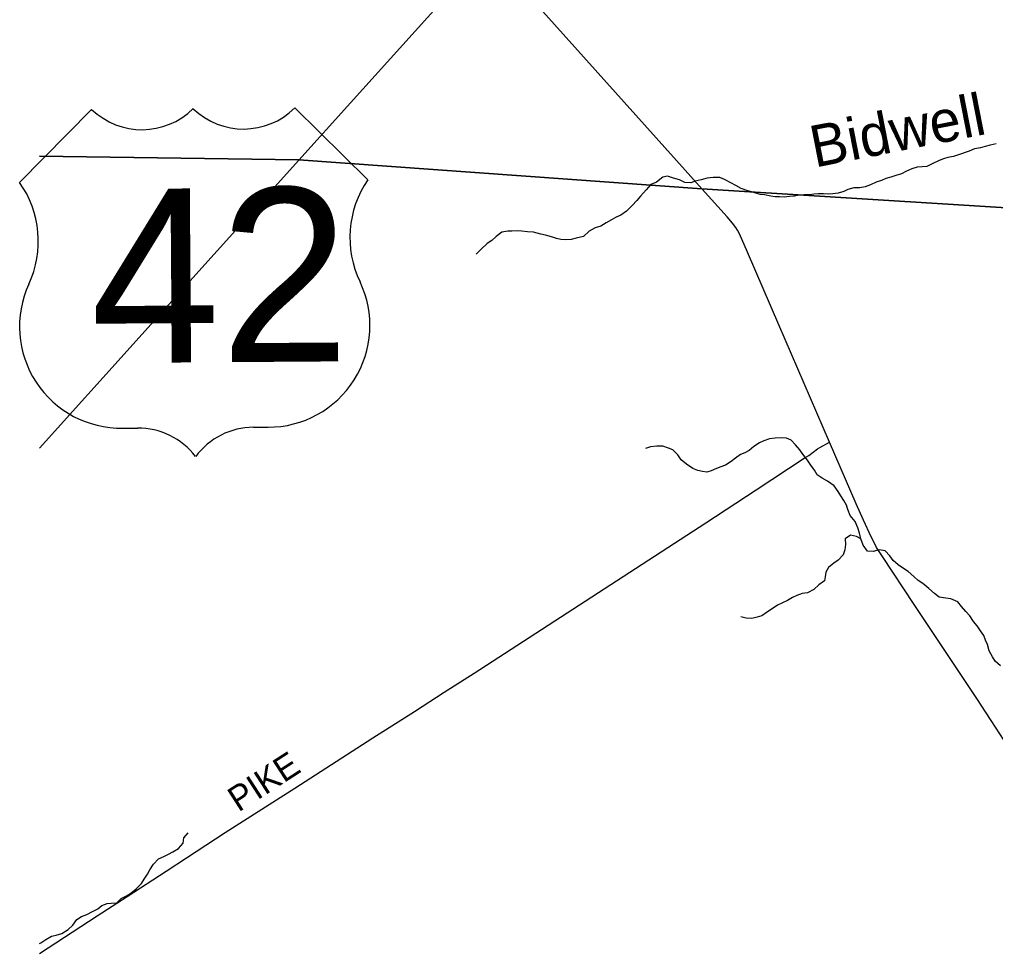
# Model space of a CAD drawing. Extents: x 114604 to 551442, y 316898 to 567001.
# Drawn here: x 114604 to 126312, y 394030 to 405241 of the extents above; entities that cross this region are included whole.
import ezdxf

# ---------------------------------------------------------------- set-up
doc = ezdxf.new("R2010")
doc.units = 0
for name, color, linetype in [('GE_P_Alignment_1000_Stations', 7, 'Continuous'), ('GE_P_Alignment_500_Bearings', 7, 'Continuous'), ('GE_P_Alignment_500_Cardinal_Points', 7, 'Continuous'), ('GE_P_Alignment_500_Distances', 7, 'Continuous'), ('PM_P_Cells', 7, 'Continuous'), ('PM_P_CL_Double_Solid', 7, 'Continuous'), ('PM_P_Stop_Line', 7, 'Continuous'), ('RD_X_RR_1', 7, 'Continuous')]:
    doc.layers.add(name, color=color, linetype=linetype)

msp = doc.modelspace()

# ---------------------------------------------------------------- linework, layer by layer
at = {"layer": 'GE_P_Alignment_1000_Stations'}
for points in [[(117956, 403554), (118576, 404240), (119979, 405801)], [(114843, 400096), (115967, 401345), (116469, 401900), (117956, 403554)]]:
    msp.add_lwpolyline(points, dxfattribs=at)
at = {"layer": 'GE_P_Alignment_500_Bearings'}
for points in [[(122792, 403206), (122590, 403434), (120534, 405730), (120339, 405951), (120260, 406047)], [(124322, 400169), (123713, 401576), (123338, 402450), (123241, 402669), (123217, 402711), (123196, 402745), (123156, 402797), (123092, 402871), (122792, 403206)], [(114843, 394030), (115537, 394481), (115896, 394713), (116363, 395017), (116608, 395180), (117070, 395482), (117905, 396014), (118844, 396617), (119342, 396934), (119699, 397166), (120059, 397395), (120571, 397725), (121846, 398557), (122838, 399201), (123440, 399595), (124015, 399975), (124071, 400009), (124123, 400049), (124177, 400087), (124205, 400104), (124322, 400169)], [(126519, 396426), (126262, 396828), (126090, 397091), (125336, 398220), (124956, 398794), (124886, 398905), (124855, 398962), (124821, 399032), (124730, 399230), (124642, 399428), (124322, 400169)]]:
    msp.add_lwpolyline(points, dxfattribs=at)
at = {"layer": 'GE_P_Alignment_500_Cardinal_Points'}
for p, q in [((115469, 404162), (114605, 403285)), ((118782, 403315), (117906, 404179)), ((115845, 400336), (116019, 400337)), ((117411, 400347), (117585, 400348))]:
    msp.add_line(p, q, dxfattribs=at)
for centre, radius, start, end in [((116074, 404788), 870, 225.984, 314.838), ((117292, 404796), 870, 225.984, 314.838), ((113612, 402580), 1218, 334.9581, 35.4119), ((119785, 402624), 1218, 145.4101, 205.8639), ((115822, 401554), 1218, 155.2429, 271.0493), ((117590, 401566), 1218, 269.7728, 25.5791), ((116025, 399467), 870, 37.2809, 90.411), ((117417, 399477), 870, 90.411, 143.5411)]:
    msp.add_arc(centre, radius, start, end, dxfattribs=at)
at = {"layer": 'GE_P_Alignment_500_Distances'}
for points in [[(114843, 403600), (117955, 403556), (122791, 403209), (132603, 402598)], [(132603, 402598), (122791, 403209), (117955, 403556), (114843, 403600)]]:
    msp.add_lwpolyline(points, dxfattribs=at)
at = {"layer": 'PM_P_Cells'}
for points in [[(126321, 403747), (126247, 403731), (126187, 403715), (126133, 403699), (126059, 403688), (125996, 403660), (125868, 403616), (125810, 403598), (125740, 403583), (125690, 403569), (125635, 403549), (125551, 403509), (125487, 403477), (125431, 403473), (125373, 403470), (125307, 403448), (125244, 403420), (125184, 403390), (125116, 403368), (125056, 403348), (124998, 403333), (124943, 403307), (124881, 403287), (124813, 403257), (124747, 403231), (124685, 403220), (124612, 403220), (124542, 403200), (124492, 403176), (124426, 403158), (124362, 403149), (124312, 403145), (124248, 403147), (124185, 403149), (124133, 403143), (124083, 403137), (124015, 403136), (123951, 403132), (123899, 403122), (123841, 403116), (123775, 403109), (123721, 403111), (123671, 403113), (123618, 403121), (123540, 403137), (123490, 403142), (123414, 403166), (123340, 403184)], [(123340, 403184), (123262, 403213), (123196, 403249), (123136, 403279), (123060, 403320), (123004, 403344), (122926, 403344), (122852, 403336), (122780, 403317), (122710, 403299), (122658, 403279), (122587, 403285), (122520, 403318), (122449, 403338), (122377, 403360), (122321, 403348), (122245, 403289), (122177, 403259), (122120, 403197), (122054, 403121), (122008, 403067), (121953, 403009), (121887, 402941), (121817, 402893), (121760, 402867), (121706, 402836), (121642, 402800), (121578, 402762), (121509, 402742), (121437, 402700), (121371, 402638), (121283, 402617), (121222, 402599), (121148, 402595), (121098, 402599), (121046, 402612), (120986, 402632), (120912, 402654), (120858, 402664), (120770, 402687), (120698, 402693), (120630, 402701), (120574, 402704), (120512, 402702), (120462, 402700), (120391, 402690), (120323, 402638), (120269, 402589), (120215, 402551), (120142, 402485), (120082, 402423)], [(124298, 399698), (124232, 399734), (124174, 399774), (124140, 399830), (124096, 399890), (124056, 399950), (124002, 400023), (123964, 400075), (123914, 400135), (123862, 400191), (123806, 400215), (123746, 400219), (123670, 400215), (123602, 400207), (123534, 400185), (123482, 400161), (123414, 400115), (123356, 400069), (123304, 400039), (123252, 400019), (123194, 399975), (123142, 399935), (123074, 399893), (123016, 399871), (122964, 399851), (122902, 399823), (122848, 399809), (122796, 399815), (122740, 399829), (122683, 399853), (122605, 399905), (122541, 399955), (122501, 400017), (122443, 400075), (122391, 400095), (122321, 400119), (122249, 400119), (122175, 400112), (122115, 400092)], [(126373, 397482), (126307, 397540), (126275, 397590), (126237, 397664), (126215, 397740), (126193, 397792), (126171, 397846), (126131, 397903), (126093, 397961), (126049, 398015), (126004, 398081), (125956, 398135), (125906, 398195), (125862, 398251), (125778, 398289), (125716, 398295), (125638, 398307), (125580, 398353), (125514, 398412), (125442, 398470), (125386, 398506), (125332, 398556), (125264, 398614), (125198, 398660), (125146, 398694), (125086, 398746), (125043, 398802), (124989, 398862), (124915, 398874), (124843, 398856), (124775, 398859), (124725, 398931), (124697, 399009), (124681, 399077), (124659, 399141), (124627, 399217), (124569, 399289), (124541, 399361), (124523, 399413), (124491, 399468), (124455, 399524), (124423, 399574), (124377, 399642), (124298, 399698)], [(124697, 399007), (124645, 399035), (124573, 399051), (124509, 399009), (124511, 398941), (124505, 398877), (124483, 398817), (124425, 398750), (124373, 398714), (124309, 398662), (124275, 398608), (124267, 398552), (124261, 398502), (124193, 398454), (124131, 398398), (124057, 398358), (123991, 398352), (123929, 398328), (123875, 398304), (123815, 398266), (123749, 398236), (123697, 398212), (123647, 398174), (123579, 398130), (123509, 398084), (123455, 398068), (123389, 398052), (123323, 398056), (123259, 398070)], [(114843, 394149), (114859, 394158), (114919, 394200), (114987, 394238), (115045, 394252), (115113, 394272), (115189, 394320), (115245, 394372), (115291, 394438), (115347, 394476), (115413, 394498), (115481, 394534), (115543, 394568), (115593, 394608), (115655, 394632), (115705, 394636), (115773, 394640), (115823, 394690), (115889, 394724), (115941, 394756), (116005, 394806), (116069, 394872), (116101, 394924), (116141, 394984), (116169, 395036), (116213, 395102), (116271, 395166), (116337, 395196), (116391, 395224), (116445, 395250), (116513, 395291), (116569, 395355), (116577, 395419), (116629, 395479)]]:
    msp.add_lwpolyline(points, dxfattribs=at)

# ---------------------------------------------------------------- texts
at = {"layer": 'GE_P_Alignment_500_Cardinal_Points'}
msp.add_text('42', height=2088.4, rotation=0.411, dxfattribs=at).set_placement((115461, 401116))
at = {"layer": 'PM_P_CL_Double_Solid'}
msp.add_text('PIKE', height=300, rotation=32.9043, dxfattribs=at).set_placement((117231, 395721))
at = {"layer": 'PM_P_Stop_Line'}
msp.add_text('Bidwell', height=500, rotation=11.0669, dxfattribs=at).set_placement((124143, 403462))
at = {"layer": 'RD_X_RR_1'}
for s, p in [('0', (116701, 402154)), ('/', (116702, 402154)), ('42', (116497, 401945))]:
    msp.add_text(s, height=1, rotation=0.411, dxfattribs=at).set_placement(p)

doc.saveas('drawing.dxf')
